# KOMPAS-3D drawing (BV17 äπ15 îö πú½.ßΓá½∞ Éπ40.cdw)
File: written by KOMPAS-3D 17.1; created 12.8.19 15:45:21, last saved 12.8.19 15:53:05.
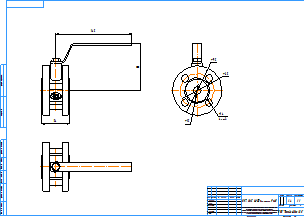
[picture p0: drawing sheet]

Sheet 1: A2, landscape

Title block, sheet 1: name: BV17 Ду15 М/Ф угл.сталь Ру40; material: Сталь 20  ГОСТ 1050-88; mass: 1,4; sheets: 1; sheet format: A2; stored path: \\adlc.lan\data\АДЛ_ПКД\3D-модели\ADL production\Краны шаровые серии BV\BV17 МФ угл.сталь Ру40\KOMPAS 2D\BV17 Ду15 МФ угл.сталь Ру40.cdw

Views: Вид 1, Проекционный вид 2, Проекционный вид 3
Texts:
  kka
  adl
  Рама для чертежей
  Лит-Масса-Масштаб
  Материал-Предприятие
  Масштаб
  Изм.
  Лист
  № докум.
  Подп.
  Дата
  Лит.
  Разраб.
  Пров.
  Т.контр.
  Листов
  Внимание! Данный продукт является объектом авторского права ООО «Торговый Дом АДЛ».
  Запрещается изменение, копирование, распространение
  (в том числе путем копирования на другие сайты и ресурсы в Интернете)
  или любое иное использование информации и объектов без предварительного
  согласия правообладателя (ООО «Торговый Дом АДЛ»).
  Н.контр.
  Утв.
  ООО "Торговый дом АДЛ"
  Изменение
  Номер документа
  Подпись
  Обозначение документа
  Наименование изделия
  Масса изделия по ГОСТ 2.109-73
  Порядковый номер листа
  Общее количество листов в документе
  Характер работы, выполненной лицом, подписавшим документ
  Наименование или индекс предприятия, выпускающего документ
  Инв. № подл.
  Подп. и дата
  Взам. инв. №
  Инв. № дубл.
  Инвентарный номер подлинника по ГОСТ 2.501-68
  Подпись принявшего подлинник в отдел технической документации
  Инвентарный номер подлинника, взамен которого выпущен данный подлинник
  Инвентарный номер дубликата по ГОСТ 2.502-68
  Подпись принявшего дубликат в отдел технической документации
  Справ. №
  Перв. примен.
  Обозначение документа, взамен или на основании которого выпущен данный документ
  Обозначение документа, в котором впервые записан данный документ
  Подпись лица, копировавшего чертеж
  Обозначение формата листа
  !Рама для чертежа
Dimensions and other numbers on the sheet: 54; 90; 145; 95; 65; 14; 4 отв.; 15; 1:1; 1; 1,4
